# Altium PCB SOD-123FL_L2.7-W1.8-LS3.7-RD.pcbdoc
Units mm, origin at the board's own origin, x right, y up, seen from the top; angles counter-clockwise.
Board outline 17.37 x 14.61 mm, 2 copper layers (Top Layer, Bottom Layer), stack 0 mm thick; 1 components, 0 nets, 2 pads, 0 vias.
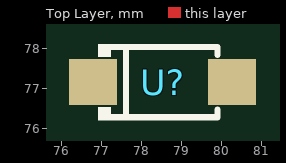
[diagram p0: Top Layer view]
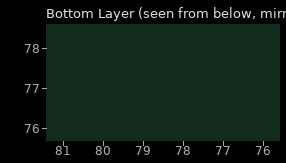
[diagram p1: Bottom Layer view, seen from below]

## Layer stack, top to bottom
Top Layer: signal copper (thickness not stored)
Bottom Layer: signal copper (thickness not stored)

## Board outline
87.22,69.85 69.85,69.85 69.85,84.462 87.22,84.462

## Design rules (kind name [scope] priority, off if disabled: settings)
PasteMaskExpansion "Paste Mask Expansion" [All] p1: expansion=0
SolderMaskExpansion "Solder Mask Expansion" [IsVia] p1: expansion=-25.4 istentingtop=TRUE
SolderMaskExpansion "Solder Mask Expansion" [All] p2: expansion=0.051 istentingtop=FALSE

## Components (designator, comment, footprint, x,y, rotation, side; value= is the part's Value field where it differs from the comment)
U? "" SOD-123FL_L2.7-W1.8-LS3.7-RD 78.535,77.16 r0 top

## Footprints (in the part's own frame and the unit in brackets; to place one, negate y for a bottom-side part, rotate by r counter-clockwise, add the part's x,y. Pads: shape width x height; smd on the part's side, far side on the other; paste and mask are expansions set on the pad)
SOD-123FL_L2.7-W1.8-LS3.7-RD [mm]
  rect 1.2x1.15 smd: 1(-1.735,0) 2(1.735,0)
  silkscreen extent -1.6,-0.95 1.38,0.95

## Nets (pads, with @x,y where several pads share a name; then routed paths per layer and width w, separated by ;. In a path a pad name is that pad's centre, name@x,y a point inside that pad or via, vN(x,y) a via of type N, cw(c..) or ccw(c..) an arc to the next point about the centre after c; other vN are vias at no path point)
pads on no net: U?.1 U?.2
